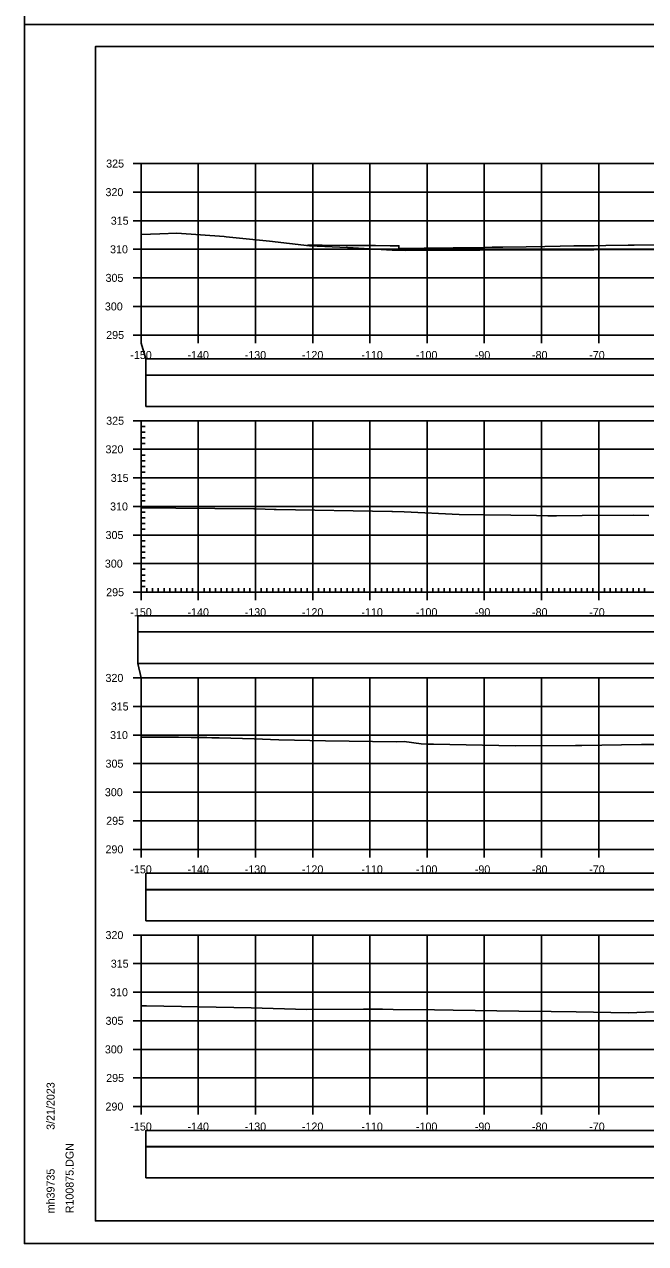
# Model space of a CAD drawing. Extents: x 1368122 to 1710785, y 373130 to 557566.
# Drawn here: x 1369851.8 to 1369960.4, y 374410.4 to 374623.7 of the extents above; entities that cross this region are included whole.
import ezdxf

# ---------------------------------------------------------------- set-up
doc = ezdxf.new("R2010")
doc.units = 0
for name, color, linetype in [('R_Alt Surface', 7, 'Continuous'), ('R_Axis', 7, 'Continuous'), ('R_Axis Annot', 7, 'Continuous'), ('R_Border', 7, 'Continuous'), ('R_Exist Surface', 7, 'Continuous'), ('R_Fin Surface', 7, 'Continuous'), ('R_Grid', 7, 'Continuous'), ('R_No Plot', 7, 'Continuous')]:
    doc.layers.add(name, color=color, linetype=linetype)

msp = doc.modelspace()

# ---------------------------------------------------------------- linework, layer by layer
for points in [[(1369873.09, 374562.33), (1370171.39, 374562.33), (1370171.39, 374565.15), (1369873.09, 374565.15)], [(1369871.69, 374517.38), (1370169.99, 374517.38), (1370169.99, 374520.2), (1369871.69, 374520.2)], [(1369873.09, 374472.33), (1370171.39, 374472.33), (1370171.39, 374475.15), (1369873.09, 374475.15)], [(1369873.09, 374466.86), (1370171.39, 374466.86), (1370171.39, 374472.27), (1369873.09, 374472.27)], [(1369873.09, 374427.33), (1370171.39, 374427.33), (1370171.39, 374430.15), (1369873.09, 374430.15)], [(1369873.09, 374421.86), (1370171.39, 374421.86), (1370171.39, 374427.27), (1369873.09, 374427.27)]]:
    msp.add_lwpolyline(points, close=True)
at = {"layer": 'R_Alt Surface'}
for p, q in [((1369872.24, 374567.94), (1369873.09, 374565.15)), ((1369872.24, 374509.34), (1369871.69, 374511.86))]:
    msp.add_line(p, q, dxfattribs=at)
for points in [[(1369873.09, 374556.81), (1370171.51, 374556.81), (1370171.51, 374562.33), (1369873.09, 374562.33)], [(1369871.69, 374511.86), (1370170.11, 374511.86), (1370170.11, 374517.38), (1369871.69, 374517.38)]]:
    msp.add_lwpolyline(points, close=True, dxfattribs=at)
at = {"layer": 'R_Axis'}
for p, q in [((1369870.84, 374599.34), (1369872.24, 374599.34)), ((1369872.24, 374569.34), (1369872.24, 374599.34)), ((1369870.84, 374594.34), (1369872.24, 374594.34)), ((1369870.84, 374589.34), (1369872.24, 374589.34)), ((1369870.84, 374584.34), (1369872.24, 374584.34)), ((1369870.84, 374579.34), (1369872.24, 374579.34)), ((1369870.84, 374574.34), (1369872.24, 374574.34)), ((1369870.84, 374569.34), (1369872.24, 374569.34)), ((1369872.24, 374569.34), (1370172.24, 374569.34)), ((1369872.24, 374567.94), (1369872.24, 374569.34)), ((1369882.24, 374567.94), (1369882.24, 374569.34)), ((1369892.24, 374567.94), (1369892.24, 374569.34)), ((1369902.24, 374567.94), (1369902.24, 374569.34)), ((1369912.24, 374567.94), (1369912.24, 374569.34)), ((1369922.24, 374567.94), (1369922.24, 374569.34)), ((1369932.24, 374567.94), (1369932.24, 374569.34)), ((1369942.24, 374567.94), (1369942.24, 374569.34)), ((1369952.24, 374567.94), (1369952.24, 374569.34)), ((1369870.84, 374554.34), (1369873.64, 374554.34)), ((1369872.24, 374524.34), (1369872.24, 374554.34)), ((1369872.24, 374553.34), (1369872.94, 374553.34)), ((1369872.24, 374552.34), (1369872.94, 374552.34)), ((1369872.24, 374551.34), (1369872.94, 374551.34)), ((1369872.24, 374550.34), (1369872.94, 374550.34)), ((1369870.84, 374549.34), (1369873.64, 374549.34)), ((1369872.24, 374548.34), (1369872.94, 374548.34)), ((1369872.24, 374547.34), (1369872.94, 374547.34)), ((1369872.24, 374546.34), (1369872.94, 374546.34)), ((1369870.84, 374544.34), (1369873.64, 374544.34)), ((1369872.24, 374545.34), (1369872.94, 374545.34)), ((1369872.24, 374543.34), (1369872.94, 374543.34)), ((1369872.24, 374542.34), (1369872.94, 374542.34)), ((1369870.84, 374539.34), (1369873.64, 374539.34)), ((1369872.24, 374541.34), (1369872.94, 374541.34)), ((1369872.24, 374540.34), (1369872.94, 374540.34)), ((1369872.24, 374538.34), (1369872.94, 374538.34)), ((1369872.24, 374537.34), (1369872.94, 374537.34)), ((1369872.24, 374536.34), (1369872.94, 374536.34)), ((1369872.24, 374535.34), (1369872.94, 374535.34)), ((1369870.84, 374534.34), (1369873.64, 374534.34)), ((1369872.24, 374533.34), (1369872.94, 374533.34)), ((1369872.24, 374532.34), (1369872.94, 374532.34)), ((1369872.24, 374531.34), (1369872.94, 374531.34)), ((1369870.84, 374529.34), (1369873.64, 374529.34)), ((1369872.24, 374530.34), (1369872.94, 374530.34)), ((1369872.24, 374528.34), (1369872.94, 374528.34)), ((1369872.24, 374527.34), (1369872.94, 374527.34)), ((1369870.84, 374524.34), (1369873.64, 374524.34)), ((1369872.24, 374526.34), (1369872.94, 374526.34)), ((1369872.24, 374522.94), (1369872.24, 374525.74)), ((1369872.24, 374525.34), (1369872.94, 374525.34)), ((1369872.24, 374524.34), (1370172.24, 374524.34)), ((1369873.24, 374524.34), (1369873.24, 374525.04)), ((1369874.24, 374524.34), (1369874.24, 374525.04)), ((1369875.24, 374524.34), (1369875.24, 374525.04)), ((1369876.24, 374524.34), (1369876.24, 374525.04)), ((1369877.24, 374524.34), (1369877.24, 374525.04)), ((1369878.24, 374524.34), (1369878.24, 374525.04)), ((1369879.24, 374524.34), (1369879.24, 374525.04)), ((1369880.24, 374524.34), (1369880.24, 374525.04)), ((1369881.24, 374524.34), (1369881.24, 374525.04)), ((1369882.24, 374522.94), (1369882.24, 374525.74)), ((1369883.24, 374524.34), (1369883.24, 374525.04)), ((1369884.24, 374524.34), (1369884.24, 374525.04)), ((1369885.24, 374524.34), (1369885.24, 374525.04)), ((1369886.24, 374524.34), (1369886.24, 374525.04)), ((1369887.24, 374524.34), (1369887.24, 374525.04)), ((1369888.24, 374524.34), (1369888.24, 374525.04)), ((1369889.24, 374524.34), (1369889.24, 374525.04)), ((1369890.24, 374524.34), (1369890.24, 374525.04)), ((1369891.24, 374524.34), (1369891.24, 374525.04)), ((1369892.24, 374522.94), (1369892.24, 374525.74)), ((1369893.24, 374524.34), (1369893.24, 374525.04)), ((1369894.24, 374524.34), (1369894.24, 374525.04)), ((1369895.24, 374524.34), (1369895.24, 374525.04)), ((1369896.24, 374524.34), (1369896.24, 374525.04)), ((1369897.24, 374524.34), (1369897.24, 374525.04)), ((1369898.24, 374524.34), (1369898.24, 374525.04)), ((1369899.24, 374524.34), (1369899.24, 374525.04)), ((1369900.24, 374524.34), (1369900.24, 374525.04)), ((1369901.24, 374524.34), (1369901.24, 374525.04)), ((1369902.24, 374522.94), (1369902.24, 374525.74)), ((1369903.24, 374524.34), (1369903.24, 374525.04)), ((1369904.24, 374524.34), (1369904.24, 374525.04)), ((1369905.24, 374524.34), (1369905.24, 374525.04)), ((1369906.24, 374524.34), (1369906.24, 374525.04)), ((1369907.24, 374524.34), (1369907.24, 374525.04)), ((1369908.24, 374524.34), (1369908.24, 374525.04)), ((1369909.24, 374524.34), (1369909.24, 374525.04)), ((1369910.24, 374524.34), (1369910.24, 374525.04)), ((1369911.24, 374524.34), (1369911.24, 374525.04)), ((1369912.24, 374522.94), (1369912.24, 374525.74)), ((1369913.24, 374524.34), (1369913.24, 374525.04)), ((1369914.24, 374524.34), (1369914.24, 374525.04)), ((1369915.24, 374524.34), (1369915.24, 374525.04)), ((1369916.24, 374524.34), (1369916.24, 374525.04)), ((1369917.24, 374524.34), (1369917.24, 374525.04)), ((1369918.24, 374524.34), (1369918.24, 374525.04)), ((1369919.24, 374524.34), (1369919.24, 374525.04)), ((1369920.24, 374524.34), (1369920.24, 374525.04)), ((1369921.24, 374524.34), (1369921.24, 374525.04)), ((1369922.24, 374522.94), (1369922.24, 374525.74)), ((1369923.24, 374524.34), (1369923.24, 374525.04)), ((1369924.24, 374524.34), (1369924.24, 374525.04)), ((1369925.24, 374524.34), (1369925.24, 374525.04)), ((1369926.24, 374524.34), (1369926.24, 374525.04)), ((1369927.24, 374524.34), (1369927.24, 374525.04)), ((1369928.24, 374524.34), (1369928.24, 374525.04)), ((1369929.24, 374524.34), (1369929.24, 374525.04)), ((1369930.24, 374524.34), (1369930.24, 374525.04)), ((1369931.24, 374524.34), (1369931.24, 374525.04)), ((1369932.24, 374522.94), (1369932.24, 374525.74)), ((1369933.24, 374524.34), (1369933.24, 374525.04)), ((1369934.24, 374524.34), (1369934.24, 374525.04)), ((1369935.24, 374524.34), (1369935.24, 374525.04)), ((1369936.24, 374524.34), (1369936.24, 374525.04)), ((1369937.24, 374524.34), (1369937.24, 374525.04)), ((1369938.24, 374524.34), (1369938.24, 374525.04)), ((1369939.24, 374524.34), (1369939.24, 374525.04)), ((1369940.24, 374524.34), (1369940.24, 374525.04)), ((1369941.24, 374524.34), (1369941.24, 374525.04)), ((1369942.24, 374522.94), (1369942.24, 374525.74)), ((1369943.24, 374524.34), (1369943.24, 374525.04)), ((1369944.24, 374524.34), (1369944.24, 374525.04)), ((1369945.24, 374524.34), (1369945.24, 374525.04)), ((1369946.24, 374524.34), (1369946.24, 374525.04)), ((1369947.24, 374524.34), (1369947.24, 374525.04)), ((1369948.24, 374524.34), (1369948.24, 374525.04)), ((1369949.24, 374524.34), (1369949.24, 374525.04)), ((1369950.24, 374524.34), (1369950.24, 374525.04)), ((1369951.24, 374524.34), (1369951.24, 374525.04)), ((1369952.24, 374522.94), (1369952.24, 374525.74)), ((1369953.24, 374524.34), (1369953.24, 374525.04)), ((1369954.24, 374524.34), (1369954.24, 374525.04)), ((1369955.24, 374524.34), (1369955.24, 374525.04)), ((1369956.24, 374524.34), (1369956.24, 374525.04)), ((1369957.24, 374524.34), (1369957.24, 374525.04)), ((1369958.24, 374524.34), (1369958.24, 374525.04)), ((1369959.24, 374524.34), (1369959.24, 374525.04)), ((1369960.24, 374524.34), (1369960.24, 374525.04)), ((1369870.84, 374509.34), (1369872.24, 374509.34)), ((1369872.24, 374479.34), (1369872.24, 374509.34)), ((1369870.84, 374504.34), (1369872.24, 374504.34)), ((1369870.84, 374499.34), (1369872.24, 374499.34)), ((1369870.84, 374494.34), (1369872.24, 374494.34)), ((1369870.84, 374489.34), (1369872.24, 374489.34)), ((1369870.84, 374484.34), (1369872.24, 374484.34)), ((1369870.84, 374479.34), (1369872.24, 374479.34)), ((1369872.24, 374479.34), (1370172.24, 374479.34)), ((1369872.24, 374477.94), (1369872.24, 374479.34)), ((1369882.24, 374477.94), (1369882.24, 374479.34)), ((1369892.24, 374477.94), (1369892.24, 374479.34)), ((1369902.24, 374477.94), (1369902.24, 374479.34)), ((1369912.24, 374477.94), (1369912.24, 374479.34)), ((1369922.24, 374477.94), (1369922.24, 374479.34)), ((1369932.24, 374477.94), (1369932.24, 374479.34)), ((1369942.24, 374477.94), (1369942.24, 374479.34)), ((1369952.24, 374477.94), (1369952.24, 374479.34)), ((1369870.84, 374464.34), (1369872.24, 374464.34)), ((1369872.24, 374434.34), (1369872.24, 374464.34)), ((1369870.84, 374459.34), (1369872.24, 374459.34)), ((1369870.84, 374454.34), (1369872.24, 374454.34)), ((1369870.84, 374449.34), (1369872.24, 374449.34)), ((1369870.84, 374444.34), (1369872.24, 374444.34)), ((1369870.84, 374439.34), (1369872.24, 374439.34)), ((1369870.84, 374434.34), (1369872.24, 374434.34)), ((1369872.24, 374434.34), (1370172.24, 374434.34)), ((1369872.24, 374432.94), (1369872.24, 374434.34)), ((1369882.24, 374432.94), (1369882.24, 374434.34)), ((1369892.24, 374432.94), (1369892.24, 374434.34)), ((1369902.24, 374432.94), (1369902.24, 374434.34)), ((1369912.24, 374432.94), (1369912.24, 374434.34)), ((1369922.24, 374432.94), (1369922.24, 374434.34)), ((1369932.24, 374432.94), (1369932.24, 374434.34)), ((1369942.24, 374432.94), (1369942.24, 374434.34)), ((1369952.24, 374432.94), (1369952.24, 374434.34))]:
    msp.add_line(p, q, dxfattribs=at)
at = {"layer": 'R_Border'}
for p, q in [((1369864.24, 374619.8), (1370180.42, 374619.8)), ((1369864.24, 374414.34), (1369864.24, 374619.8)), ((1369864.24, 374414.34), (1369864.24, 374414.34)), ((1370180.42, 374414.34), (1369864.24, 374414.34))]:
    msp.add_line(p, q, dxfattribs=at)
at = {"layer": 'R_Exist Surface'}
for points in [[(1369872.24, 374586.93), (1369875.51, 374587.05), (1369878.48, 374587.18), (1369886.74, 374586.55), (1369887.08, 374586.52), (1369894.66, 374585.76), (1369901.66, 374584.97), (1369908.3, 374584.64), (1369916.12, 374584.18), (1369917.4, 374584.16), (1369918.5, 374584.13), (1369926.9, 374584.18), (1369931.47, 374584.2), (1369943, 374584.24), (1369951.38, 374584.27), (1369956.89, 374584.29), (1369969.34, 374584.33)], [(1369872.24, 374539.12), (1369873.84, 374539.11), (1369878.33, 374539.07), (1369891.93, 374538.93), (1369892.38, 374538.93), (1369895.49, 374538.8), (1369895.5, 374538.8), (1369895.51, 374538.8), (1369895.52, 374538.8), (1369895.55, 374538.8), (1369895.83, 374538.8), (1369916.09, 374538.46), (1369916.21, 374538.47), (1369918.2, 374538.39), (1369927.82, 374537.91), (1369941.34, 374537.75), (1369943.37, 374537.71), (1369944.87, 374537.71), (1369949.37, 374537.76), (1369958.3, 374537.84), (1369961.01, 374537.76)], [(1369872.24, 374499), (1369876.65, 374498.97), (1369878.07, 374498.96), (1369878.79, 374498.95), (1369880.97, 374498.93), (1369883.7, 374498.91), (1369884.59, 374498.88), (1369885.91, 374498.88), (1369892.01, 374498.67), (1369896.31, 374498.48), (1369904.49, 374498.33), (1369916.85, 374498.14), (1369918.25, 374498.2), (1369921.22, 374497.81), (1369922.24, 374497.76), (1369923.33, 374497.75), (1369937.63, 374497.45), (1369948.16, 374497.51), (1369949.28, 374497.52), (1369959.72, 374497.68), (1369962.37, 374497.68)], [(1369872.24, 374451.95), (1369873.18, 374451.96), (1369891.48, 374451.6), (1369901.17, 374451.34), (1369911.14, 374451.35), (1369914.42, 374451.36), (1369916.3, 374451.32), (1369923.52, 374451.25), (1369926.82, 374451.22), (1369938.3, 374451.03), (1369943.93, 374450.97), (1369948.27, 374450.93), (1369957.41, 374450.76), (1369964.95, 374451.05)]]:
    msp.add_lwpolyline(points, dxfattribs=at)
at = {"layer": 'R_Fin Surface'}
msp.add_lwpolyline([(1369901.3, 374585.01), (1369901.47, 374585.04), (1369901.58, 374585.06), (1369903.92, 374585.04), (1369908.11, 374585.01), (1369909.86, 374585), (1369910.83, 374585), (1369913.23, 374584.98), (1369915.8, 374584.96), (1369916.1, 374584.96), (1369916.38, 374584.96), (1369917.11, 374584.96), (1369917.31, 374584.96), (1369917.31, 374584.59), (1369917.31, 374584.46), (1369917.99, 374584.47), (1369919.16, 374584.49), (1369921.74, 374584.53), (1369926.81, 374584.6), (1369927.69, 374584.62), (1369932.14, 374584.68), (1369933.63, 374584.71), (1369935.5, 374584.73), (1369939.57, 374584.79), (1369942.8, 374584.84), (1369945.51, 374584.88), (1369947.88, 374584.92), (1369950.83, 374584.96), (1369951.22, 374584.97), (1369951.46, 374584.97), (1369953.46, 374585), (1369957.4, 374585.06), (1369957.63, 374585.06), (1369958.38, 374585.07), (1369958.44, 374585.07), (1369962.52, 374585.13)], dxfattribs=at)
at = {"layer": 'R_Grid'}
for p, q in [((1369872.24, 374599.34), (1370172.24, 374599.34)), ((1369872.24, 374569.34), (1369872.24, 374599.34)), ((1369882.24, 374569.34), (1369882.24, 374599.34)), ((1369892.24, 374569.34), (1369892.24, 374599.34)), ((1369902.24, 374569.34), (1369902.24, 374599.34)), ((1369912.24, 374569.34), (1369912.24, 374599.34)), ((1369922.24, 374569.34), (1369922.24, 374599.34)), ((1369932.24, 374569.34), (1369932.24, 374599.34)), ((1369942.24, 374569.34), (1369942.24, 374599.34)), ((1369952.24, 374569.34), (1369952.24, 374599.34)), ((1369872.24, 374594.34), (1370172.24, 374594.34)), ((1369872.24, 374589.34), (1370172.24, 374589.34)), ((1369872.24, 374584.34), (1370172.24, 374584.34)), ((1369872.24, 374579.34), (1370172.24, 374579.34)), ((1369872.24, 374574.34), (1370172.24, 374574.34)), ((1369872.24, 374569.34), (1370172.24, 374569.34)), ((1369872.24, 374554.34), (1370172.24, 374554.34)), ((1369872.24, 374524.34), (1369872.24, 374554.34)), ((1369882.24, 374524.34), (1369882.24, 374554.34)), ((1369892.24, 374524.34), (1369892.24, 374554.34)), ((1369902.24, 374524.34), (1369902.24, 374554.34)), ((1369912.24, 374524.34), (1369912.24, 374554.34)), ((1369922.24, 374524.34), (1369922.24, 374554.34)), ((1369932.24, 374524.34), (1369932.24, 374554.34)), ((1369942.24, 374524.34), (1369942.24, 374554.34)), ((1369952.24, 374524.34), (1369952.24, 374554.34)), ((1369872.24, 374549.34), (1370172.24, 374549.34)), ((1369872.24, 374544.34), (1370172.24, 374544.34)), ((1369872.24, 374539.34), (1370172.24, 374539.34)), ((1369872.24, 374534.34), (1370172.24, 374534.34)), ((1369872.24, 374529.34), (1370172.24, 374529.34)), ((1369872.24, 374524.34), (1370172.24, 374524.34)), ((1369872.24, 374509.34), (1370172.24, 374509.34)), ((1369872.24, 374479.34), (1369872.24, 374509.34)), ((1369882.24, 374479.34), (1369882.24, 374509.34)), ((1369892.24, 374479.34), (1369892.24, 374509.34)), ((1369902.24, 374479.34), (1369902.24, 374509.34)), ((1369912.24, 374479.34), (1369912.24, 374509.34)), ((1369922.24, 374479.34), (1369922.24, 374509.34)), ((1369932.24, 374479.34), (1369932.24, 374509.34)), ((1369942.24, 374479.34), (1369942.24, 374509.34)), ((1369952.24, 374479.34), (1369952.24, 374509.34)), ((1369872.24, 374504.34), (1370172.24, 374504.34)), ((1369872.24, 374499.34), (1370172.24, 374499.34)), ((1369872.24, 374494.34), (1370172.24, 374494.34)), ((1369872.24, 374489.34), (1370172.24, 374489.34)), ((1369872.24, 374484.34), (1370172.24, 374484.34)), ((1369872.24, 374479.34), (1370172.24, 374479.34)), ((1369872.24, 374464.34), (1370172.24, 374464.34)), ((1369872.24, 374434.34), (1369872.24, 374464.34)), ((1369882.24, 374434.34), (1369882.24, 374464.34)), ((1369892.24, 374434.34), (1369892.24, 374464.34)), ((1369902.24, 374434.34), (1369902.24, 374464.34)), ((1369912.24, 374434.34), (1369912.24, 374464.34)), ((1369922.24, 374434.34), (1369922.24, 374464.34)), ((1369932.24, 374434.34), (1369932.24, 374464.34)), ((1369942.24, 374434.34), (1369942.24, 374464.34)), ((1369952.24, 374434.34), (1369952.24, 374464.34)), ((1369872.24, 374459.34), (1370172.24, 374459.34)), ((1369872.24, 374454.34), (1370172.24, 374454.34)), ((1369872.24, 374449.34), (1370172.24, 374449.34)), ((1369872.24, 374444.34), (1370172.24, 374444.34)), ((1369872.24, 374439.34), (1370172.24, 374439.34)), ((1369872.24, 374434.34), (1370172.24, 374434.34))]:
    msp.add_line(p, q, dxfattribs=at)
at = {"layer": 'R_No Plot'}
for p, q in [((1369851.84, 374623.69), (1370185.17, 374623.69)), ((1369851.84, 374410.36), (1370185.17, 374410.36))]:
    msp.add_line(p, q, dxfattribs=at)
for points in [[(1369851.83, 374837.03), (1370185.17, 374837.03), (1370185.17, 374623.69), (1369851.83, 374623.69)], [(1369851.83, 374623.69), (1370185.17, 374623.69), (1370185.17, 374410.35), (1369851.83, 374410.35)], [(1370098.16, 374619.8), (1370117.78, 374619.8), (1370117.78, 374609.92), (1370133.89, 374609.92), (1370157.09, 374609.92), (1370157.21, 374581.76), (1370180.42, 374581.76), (1370180.42, 374414.34), (1369864.24, 374414.34), (1369864.24, 374619.8)]]:
    msp.add_lwpolyline(points, close=True, dxfattribs=at)

# ---------------------------------------------------------------- texts
at = {"layer": 'R_Axis Annot'}
for s, p in [('325', (1369866.13, 374598.64)), ('320', (1369866.01, 374593.64)), ('315', (1369866.93, 374588.64)), ('310', (1369866.81, 374583.64)), ('305', (1369866.02, 374578.64)), ('300', (1369865.9, 374573.64)), ('295', (1369866.13, 374568.64)), ('-150', (1369870.35, 374565.14)), ('-140', (1369880.35, 374565.14)), ('-130', (1369890.35, 374565.14)), ('-120', (1369900.35, 374565.14)), ('-110', (1369910.75, 374565.14)), ('-100', (1369920.29, 374565.14)), ('-90', (1369930.58, 374565.14)), ('-80', (1369940.58, 374565.14)), ('-70', (1369950.58, 374565.14)), ('325', (1369866.13, 374553.64)), ('320', (1369866.01, 374548.64)), ('315', (1369866.93, 374543.64)), ('310', (1369866.81, 374538.64)), ('305', (1369866.02, 374533.64)), ('300', (1369865.9, 374528.64)), ('295', (1369866.13, 374523.64)), ('-150', (1369870.35, 374520.14)), ('-140', (1369880.35, 374520.14)), ('-130', (1369890.35, 374520.14)), ('-120', (1369900.35, 374520.14)), ('-110', (1369910.75, 374520.14)), ('-100', (1369920.29, 374520.14)), ('-90', (1369930.58, 374520.14)), ('-80', (1369940.58, 374520.14)), ('-70', (1369950.58, 374520.14)), ('320', (1369866.01, 374508.64)), ('315', (1369866.93, 374503.64)), ('310', (1369866.81, 374498.64)), ('305', (1369866.02, 374493.64)), ('300', (1369865.9, 374488.64)), ('295', (1369866.13, 374483.64)), ('290', (1369866.01, 374478.64)), ('-150', (1369870.35, 374475.14)), ('-140', (1369880.35, 374475.14)), ('-130', (1369890.35, 374475.14)), ('-120', (1369900.35, 374475.14)), ('-110', (1369910.75, 374475.14)), ('-100', (1369920.29, 374475.14)), ('-90', (1369930.58, 374475.14)), ('-80', (1369940.58, 374475.14)), ('-70', (1369950.58, 374475.14)), ('320', (1369866.01, 374463.64)), ('315', (1369866.93, 374458.64)), ('310', (1369866.81, 374453.64)), ('305', (1369866.02, 374448.64)), ('300', (1369865.9, 374443.64)), ('295', (1369866.13, 374438.64)), ('290', (1369866.01, 374433.64)), ('-150', (1369870.35, 374430.14)), ('-140', (1369880.35, 374430.14)), ('-130', (1369890.35, 374430.14)), ('-120', (1369900.35, 374430.14)), ('-110', (1369910.75, 374430.14)), ('-100', (1369920.29, 374430.14)), ('-90', (1369930.58, 374430.14)), ('-80', (1369940.58, 374430.14)), ('-70', (1369950.58, 374430.14))]:
    msp.add_text(s, height=1.4, dxfattribs=at).set_placement(p)
at = {"layer": 'R_Border'}
for s, p in [('3/21/2023', (1369857.11, 374430.26)), ('R100875.DGN', (1369860.43, 374415.66)), ('mh39735', (1369857.11, 374415.66))]:
    msp.add_text(s, height=1.4, rotation=90, dxfattribs=at).set_placement(p)

doc.saveas('drawing.dxf')
